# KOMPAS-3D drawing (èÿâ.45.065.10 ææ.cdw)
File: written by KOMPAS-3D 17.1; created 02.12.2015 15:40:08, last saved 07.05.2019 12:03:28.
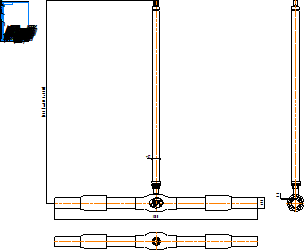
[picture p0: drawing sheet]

Sheet 1: A4, portrait

Title block, sheet 1: name: КШГ.45.065.10 СС; material: Внимание! Данный продукт является объектом авторского права ООО «Торговый Дом АДЛ». / Запрещается изменение, копирование, распространение / (в том числе путем копирования на другие сайты и ресурсы в Интернете) / или любое иное использование информации и объектов без предварительного / согласия правообладателя (ООО «Торговый Дом АДЛ»).; sheets: 1; organisation: ООО "Торговый дом АДЛ"; sheet format: A4; stored path: C:\Users\kka\KOMPAS_Work\Модели кранов для исследований\DN50\С удлинением\КШГ.32.050.40 СС ГЧ _ Шаровой кран БИВАЛ Ду50 Ру4 МПа редуцированный под приварку, с удлинением штока H=1100.cdw; drawn by: Климкович К.А.; drawn by, date: 02.12.15

Views: Вид 1, Проекционный вид 2, Проекционный вид 3
Referenced files in C:\Users\kka\KOMPAS_Work\Модели кранов для исследований\DN80\С удлинением\: КШТ.22.080.25 СС.a3d, КШГ.35.065.25 СС.a3d!КШГ.45.065.10 СС!Деталь (локальная).m3d
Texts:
  Klimkovich
  ADL
  (от 297 до 5000)
Dimensions and other numbers on the sheet: 1500; 75; 57; 6,8; 1:1; 1; 02.12.15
